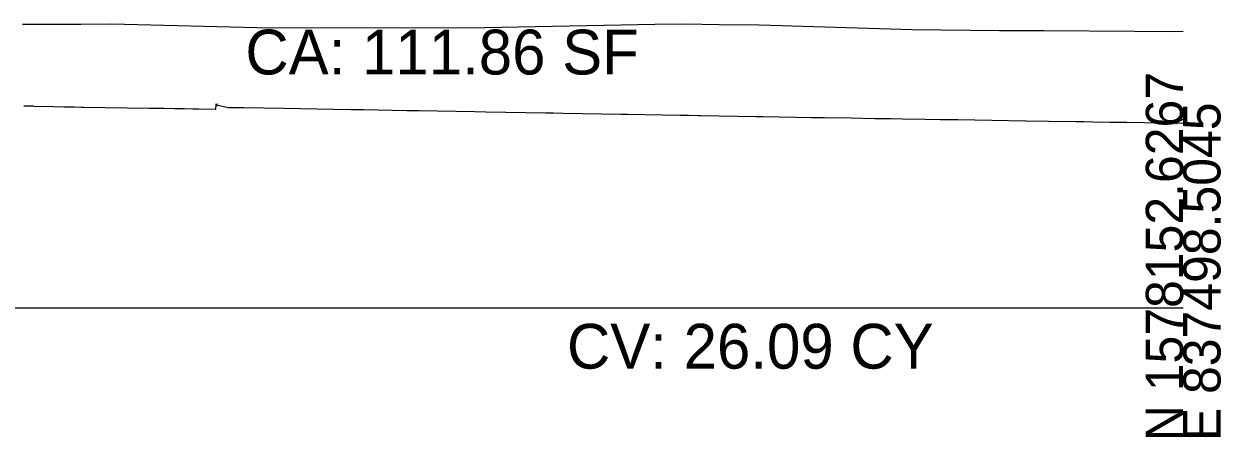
# Model space of a CAD drawing. Extents: x -26 to 303, y -16 to 6048.
# Drawn here: x 213.2 to 302.8, y 4990.3 to 5021.3 of the extents above; entities that cross this region are included whole.
import ezdxf

# ---------------------------------------------------------------- set-up
doc = ezdxf.new("R2010")
doc.units = 0
for name, color, linetype in [('DTM_TEMP_DROP', 7, 'Continuous'), ('DTM_X_FLOW_ARROWS', 7, 'Continuous'), ('DTM_X_GROUND', 7, 'Continuous'), ('XS_CELL', 7, 'Continuous'), ('XS_P_GROUND', 7, 'Continuous'), ('XS_SHEET_EW_TX_AREA', 7, 'Continuous'), ('XS_SHEET_EW_TX_VOLUME', 7, 'Continuous')]:
    doc.layers.add(name, color=color, linetype=linetype)

msp = doc.modelspace()

# ---------------------------------------------------------------- linework, layer by layer
at = {"layer": 'DTM_X_GROUND'}
for points in [[(213.045, 5021.268), (215.433, 5021.276), (217.42, 5021.283), (219.684, 5021.291), (231.606, 5021.003), (237.689, 5021.017), (241.637, 5021.001), (247.648, 5021.014), (260.409, 5021.28), (262.673, 5021.287), (265.245, 5021.257), (268.238, 5021.223), (279.698, 5020.866), (286.244, 5020.808), (289.531, 5020.799), (296.362, 5020.737), (299.349, 5020.729), (300, 5020.749)], [(213.045, 5021.256), (215.433, 5021.276), (217.42, 5021.283), (219.684, 5021.291), (231.606, 5021.003), (237.689, 5021.017), (241.637, 5021.001), (247.648, 5021.014), (260.409, 5021.28), (262.673, 5021.287), (265.245, 5021.257), (268.238, 5021.223), (279.698, 5020.866), (286.244, 5020.808), (289.531, 5020.799), (296.362, 5020.737), (299.349, 5020.729), (300, 5020.749)]]:
    msp.add_lwpolyline(points, dxfattribs=at)
at = {"layer": 'XS_CELL'}
msp.add_line((150, 5000), (300, 5000), dxfattribs=at)
at = {"layer": 'XS_P_GROUND'}
for points in [[(213.883, 5015.112), (213.871, 5015.112), (213.515, 5015.117), (213.366, 5015.119), (213.322, 5015.12), (213.156, 5015.122)], [(213.883, 5015.112), (215.375, 5015.089), (216.133, 5015.078), (216.872, 5015.067), (216.931, 5015.066), (217.459, 5015.058), (217.625, 5015.056), (222.511, 5014.982), (222.817, 5014.978), (223.568, 5014.966), (223.645, 5014.965), (224.435, 5014.953), (225.184, 5014.942), (225.812, 5014.933), (226.229, 5014.926), (227.506, 5014.907), (227.531, 5014.907), (227.563, 5015.22), (227.563, 5015.224)], [(227.563, 5015.224), (227.563, 5015.276), (227.579, 5015.224)], [(227.579, 5015.224), (227.584, 5015.223), (228.467, 5015.035), (229.636, 5015.015), (232.616, 5014.964), (236.372, 5014.899), (237.668, 5014.877), (238.365, 5014.865), (238.595, 5014.861), (241.836, 5014.805), (242.72, 5014.79), (246.925, 5014.718), (247.771, 5014.704), (252.239, 5014.627), (252.823, 5014.617), (253.545, 5014.605), (257.875, 5014.53), (258.374, 5014.522), (262.284, 5014.455), (262.926, 5014.443), (262.939, 5014.443), (263.678, 5014.431), (263.837, 5014.428), (267.978, 5014.357), (268.543, 5014.347), (272.15, 5014.285), (272.888, 5014.274), (273.029, 5014.271), (273.108, 5014.27), (273.123, 5014.27), (275.133, 5014.238), (276.891, 5014.21), (277.21, 5014.205), (278.08, 5014.191), (278.976, 5014.177), (280.676, 5014.15), (281.822, 5014.132), (283.131, 5014.111), (285.677, 5014.071), (288.182, 5014.031), (288.203, 5014.031), (288.229, 5014.031), (289.924, 5014.004), (291.975, 5013.971), (292.59, 5013.962), (293.233, 5013.951), (294.518, 5013.931), (295.782, 5013.911), (297.106, 5013.89), (298.284, 5013.871), (300, 5013.844)], [(299.432, 5013.853), (300, 5014.136)]]:
    msp.add_lwpolyline(points, dxfattribs=at)

# ---------------------------------------------------------------- texts
at = {"layer": 'DTM_TEMP_DROP'}
for p in [(227.485, 5015.104), (227.501, 5015.104)]:
    msp.add_text('X', height=0.24, dxfattribs=at).set_placement(p)
at = {"layer": 'DTM_X_FLOW_ARROWS'}
msp.add_text('X', height=0.24, dxfattribs=at).set_placement((299.354, 5013.733))
at = {"layer": 'XS_CELL'}
for s, p in [('N 1578152.6267', (300, 4990)), ('E 837498.5045', (302.8, 4990))]:
    msp.add_text(s, height=2.8, rotation=90, dxfattribs=at).set_placement(p)
at = {"layer": 'XS_SHEET_EW_TX_AREA'}
msp.add_text('CA: 111.86 SF', height=3.36, dxfattribs=at).set_placement((229.747, 5017.5))
at = {"layer": 'XS_SHEET_EW_TX_VOLUME'}
msp.add_text('CV: 26.09 CY', height=3.36, dxfattribs=at).set_placement((253.839, 4995.44))

doc.saveas('drawing.dxf')
